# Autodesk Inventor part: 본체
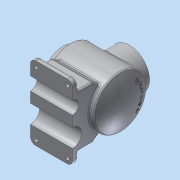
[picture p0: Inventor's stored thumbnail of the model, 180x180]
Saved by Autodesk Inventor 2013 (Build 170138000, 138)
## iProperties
Created: 2018-08
Part Number: 본체
Material: 알루미늄 6061
Document SubType Name: Modeling
Designer: dgall
Density: 2.71 g/cm^3
Mass: 1886.04 g
Surface Area: 1087.45 cm^2
Volume: 695.956 cm^3
Author: dgall
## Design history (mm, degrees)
sketch "스케치1"
  geometry: L1 (0, 0)-(120, 0); L2 (0, 0)-(0, 38); L3 (0, 38)-(12, 38); L4 (12, 38)-(12, 50); L5 (12, 50)-(108.671, 50); A1 r 116 centre (4, 0) between (120, 0) and (108.671, 50)
  constraints: 11 end point, 2 parallel, 2 perpendicular, 2 point on circle, 1 centre point, 1 horizontal, 1 horizontal alignment
  dimensions: "d0" = 120 distance of L1.start L1.end; "d1" = 116 radius of A1; "d2" = 76 diameter of L3 L1; "d3" = 100 diameter of L5 L1; "d4" = 108 distance from line of L1.end L4
revolve "회전1" sketch "스케치1" stored, may be unused: angle "d5" = 90 deg
node "작업 평면1"
sketch "스케치2"
  geometry: L1 (-12, 50)-(-12, -50) reference; C1 r 38 at (-62, 0); 1 further point
  constraints: 1 centre point, 1 horizontal alignment
  dimensions: "d7" = 76 diameter of C1; "d9" = 50 distance from line of L1 C1.centre
extrude "돌출1" join sketch "스케치2" stored distance "d10" = 10; taper "d11" = 0 deg
node "작업 평면2"
sketch "스케치3"
  geometry: L1 (-40.304, -29.59)-(-50, -43.437); L2 (-50, -43.437)-(-50, -72); L3 (-50, -72)-(-70, -72); L4 (-70, -72)-(-70, -82); L5 (-70, -82)-(70, -82); L6 (70, -82)-(70, -72); L7 (70, -72)-(50, -72); L8 (50, -72)-(50, -43.437); L9 (50, -43.437)-(40.304, -29.59); L10 (-50, -43.437)-(-70, -72); A1 r 50 centre (0, 0) between (-40.304, -29.59) and (40.304, -29.59) reference; 2 further points
  constraints: 20 end point, 6 perpendicular, 3 horizontal alignment, 2 point on circle, 1 collinear, 1 midpoint, 1 vertical, 1 vertical alignment
  dimensions: "d13" = 10 distance of L5.end L6.end; "d15" = 82 distance from line of L5 point (0, 0); "d16" = 20 distance between parallel lines of L2 L4; "d17" = 20 distance between parallel lines of L6 L8; "d19" = 140 distance between parallel lines of L6 L4; "d20" = 35 deg angle of L1 L4
extrude "돌출2" join sketch "스케치3" distance "d21" = 80; taper "d22" = 0 deg
sketch "스케치4"
  geometry: L1 (-70, -82)-(70, -82) reference; A1 r 50 centre (0, 0) between (-40.304, -29.59) and (40.304, -29.59) reference; A2 r 17.5 centre (-22.5, -82) between (-5, -82) and (-40, -82); A3 r 12.5 centre (27.5, -82) between (40, -82) and (15, -82)
  constraints: 6 point on line, 4 point on circle, 2 centre point
  dimensions: "d24" = 12.5 radius of A3; "d26" = 17.5 radius of A2; "d27" = 22.5 horizontal distance of A1.centre A2.centre; "d28" = 27.5 horizontal distance of A3.centre A1.centre
extrude "돌출3" cut sketch "스케치4" stored distance "d29" = 80; taper "d30" = 0 deg
sketch "스케치5"
  geometry: L1 (0, -38)-(0, 38) reference; L2 (0, 38)-(12, 38) reference; L3 (12, 38)-(12, 50) reference; L4 (12, 50)-(24, 50) reference; L5 (24, 50)-(24, 65) reference; L6 (24, 65)-(100, 65) reference; L7 (100, 65)-(100, 50) reference; L8 (100, 50)-(108.671, 50) reference; L9 (108.671, -50)-(100, -50) reference; L10 (100, -50)-(100, -82) reference; L11 (100, -82)-(20, -82) reference; L12 (20, -82)-(20, -50) reference; L13 (20, -50)-(12, -50) reference; L14 (12, -50)-(12, -38) reference; L15 (12, -38)-(0, -38) reference; L16 (0, 0)-(120, 0); L17 (102.163, 40)-(22, 40); L18 (22, 27)-(0, 27); L19 (22, 27)-(22, 40); L20 (0, 27)-(0, 0); A1 r 116 centre (4, 0) between (108.671, -50) and (108.671, 50) reference; A2 r 106 centre (4, 0) between (110, 0) and (102.163, 40)
  constraints: 10 end point, 3 point on circle, 2 point on line, 1 centre point, 1 collinear, 1 perpendicular
  dimensions: "d31" = 54 diameter of L18 L16; "d33" = 22 distance between parallel lines of L19 L1; "d34" = 10 radial gap between concentric circles of A1 A2; "d35" = 80 diameter of L17 L16
revolve "회전2" sketch "스케치5" stored, may be unused: angle "d36" = 90 deg
sketch "스케치6"
  geometry: C1 r 38 at (0, 0) reference; C2 r 27 at (0, 0); 1 further point
  constraints: 1 centre point, 1 coincident
  dimensions: "d37" = 54 diameter of C2
extrude "돌출4" cut sketch "스케치6" stored distance "d38" = 80; taper "d39" = 0 deg
fillet "모깎기1" dims "d40" = 10
fillet "모깎기2" dims "d41" = 3
fillet "모깎기3" dims "d42" = 3
fillet "모깎기4" dims "d43" = 3
fillet "모깎기5" dims "d44" = 3
fillet "모깎기6" dims "d45" = 3
fillet "모깎기7" dims "d46" = 3
sketch "스케치7"
  geometry: L1 (80, 100)-(80, 80) reference; L2 (80, 80)-(0, 80) reference; L3 (0, 80)-(0, 100) reference; L4 (10, 110)-(70, 110) reference; L5 (80, 55)-(80, 35) reference; L6 (80, 35)-(0, 35) reference; L7 (0, 35)-(0, 55) reference; L8 (0, 55)-(80, 55) reference; L9 (80, 0)-(80, -20) reference; L10 (70, -30)-(10, -30) reference; L11 (0, -20)-(0, 0) reference; L12 (0, 0)-(80, 0) reference; C1 r 4 at (10, -20); C2 r 4 at (70, -20); C3 r 4 at (10, 100); C4 r 4 at (70, 100); A1 r 10 centre (70, -20) between (70, -30) and (80, -20) reference; A2 r 10 centre (10, -20) between (0, -20) and (10, -30) reference; A3 r 10 centre (10, 100) between (10, 110) and (0, 100) reference; A4 r 10 centre (70, 100) between (80, 100) and (70, 110) reference; A5 r 10 centre (70, -20) between (70, -30) and (80, -20) reference; A6 r 10 centre (10, -20) between (0, -20) and (10, -30) reference; 1 further point
  constraints: 4 centre point, 4 coincident
  dimensions: "d47" = 8 diameter of C1; "d48" = 8 diameter of C2; "d49" = 8 diameter of C3; "d50" = 8 diameter of C4
extrude "돌출5" cut sketch "스케치7" distance "d51" = 10; taper "d52" = 0 deg
fillet "모깎기8" dims "d53" = 3
fillet "모깎기9" dims "d54" = 3
sketch "스케치8"
  geometry: C1 r 27 at (0, 0) reference; 1 further point
  constraints: 1 vertical alignment
  dimensions: "d55" = 32.5 distance of C1.centre point (0, 32.5)
hole "구멍1" sketch "스케치8" at (0, 32.5) diameter "d56" = 3.242; stored, may be unused: countersink angle "d60" = 90 deg, drill point angle "d62" = 118 deg; dims "d57" = 8, "d58" = 4, "d59" = 2, "d61" = 10
sketch "스케치9"
  geometry: C1 r 27 at (0, 0) reference; 2 further points
  constraints: 1 vertical alignment
  dimensions: "d66" = 32.5 distance of C1.centre point (0, 32.5)
hole "구멍2" sketch "스케치9" at (0, 32.5) diameter "d67" = 3.242; stored, may be unused: countersink angle "d71" = 90 deg, drill point angle "d73" = 118 deg; dims "d68" = 8, "d69" = 4, "d70" = 2, "d72" = 10
chamfer "모따기1" distance "d77" = 1; stored, may be unused: second distance "d78" = 2, angle "d79" = 45 deg
node "작업 평면3"
sketch "스케치10"
  geometry: C1 r 32.5 at (0, 0); 1 further point
  constraints: 1 centre point, 1 coincident, 1 other
  dimensions: "d80" = 65 diameter of C1
feature "엠보싱1" sketch "스케치10" dims "d13" = 10, "d15" = 82, "d16" = 20, "d17" = 20, "d19" = 140, "d20" = 35 deg, "d81" = 0.5, "d82" = 0
node "솔리드1"
pattern_circular "원형 패턴1" dims angle "d64" = 360 deg
pattern_circular "원형 패턴2" dims angle "d75" = 360 deg
node "절단 모서리 투영1"
node "절단 모서리 투영2"
node "절단 모서리 투영3"
other parameters: "d6" = 65, "d12" = -8
